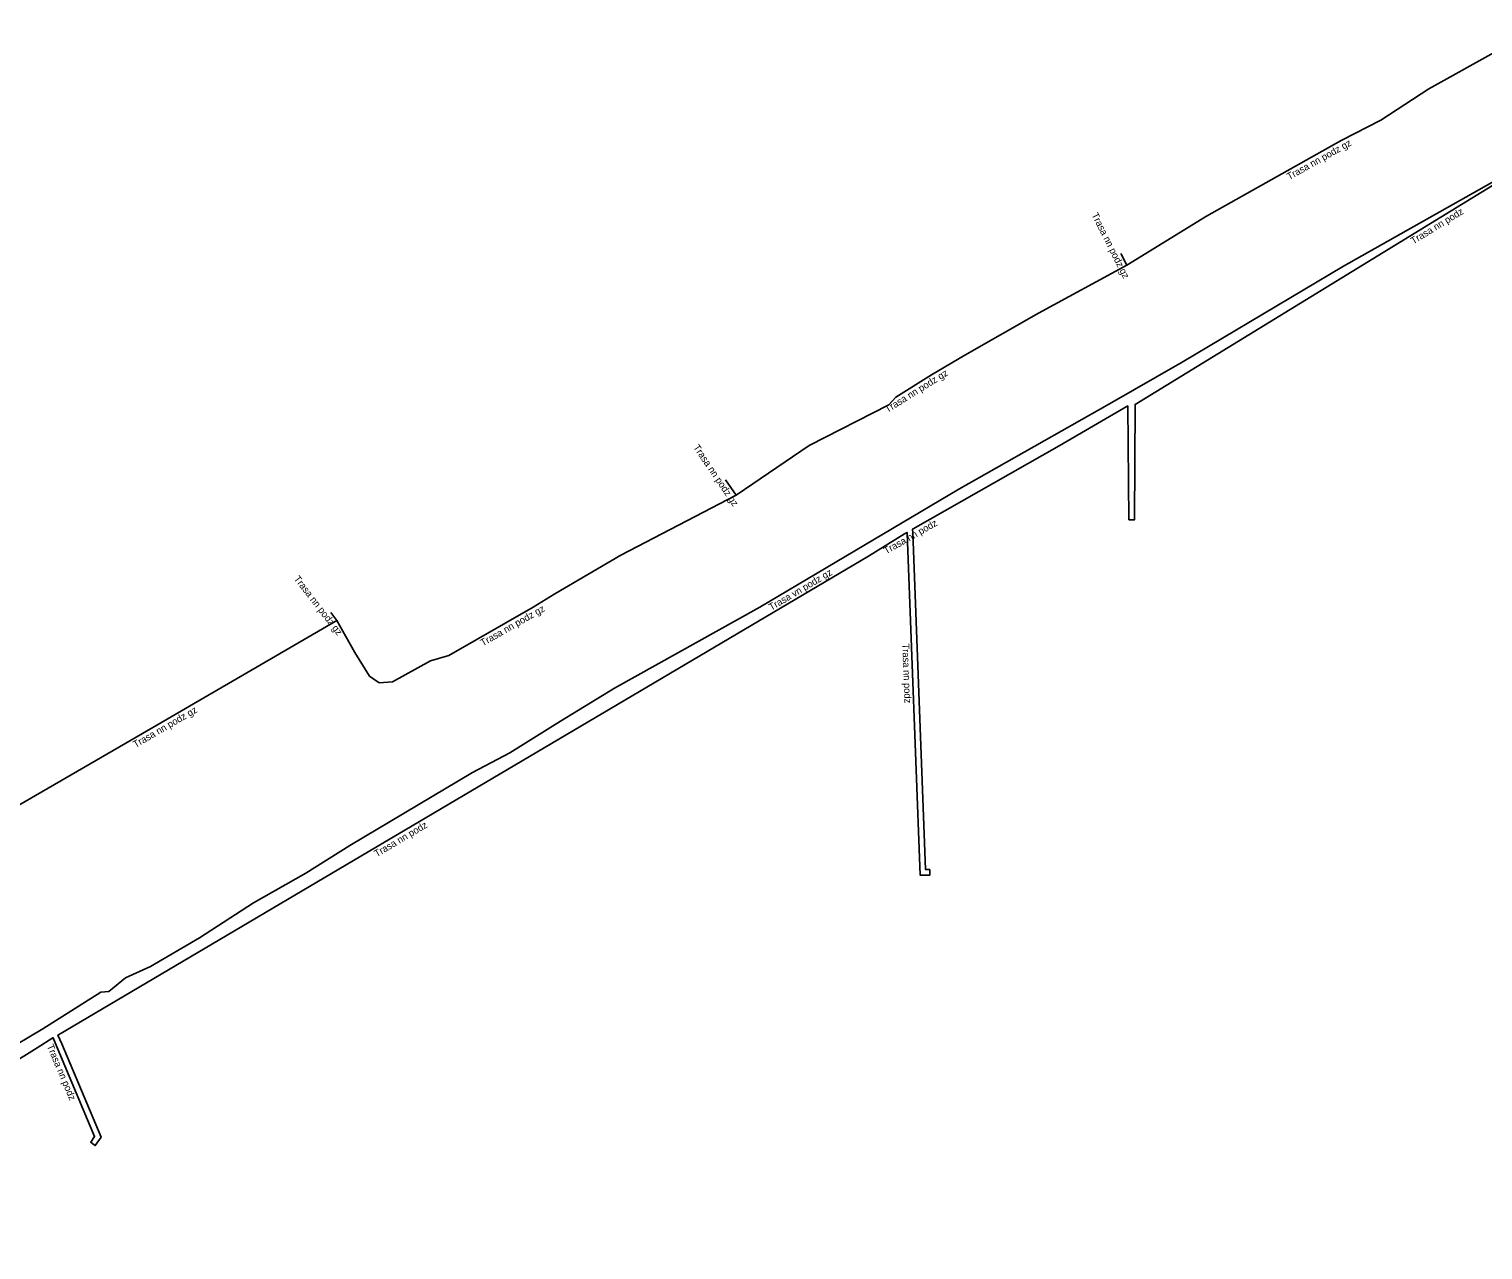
# Model space of a CAD drawing. Extents: x -689216 to -688745, y -973188 to -972893.
# Drawn here: x -688948.2 to -688844.2, y -973043.9 to -972956.5 of the extents above; entities that cross this region are included whole.
import ezdxf

# ---------------------------------------------------------------- set-up
doc = ezdxf.new("R2010")
doc.units = 0
for name, color, linetype in [('Popiskový text - Ostatní atributy Trasy', 7, 'Continuous'), ('Spojnice NN', 7, 'Continuous'), ('Spojnice VN', 7, 'Continuous')]:
    doc.layers.add(name, color=color, linetype=linetype)

msp = doc.modelspace()

# ---------------------------------------------------------------- linework, layer by layer
at = {"layer": 'Spojnice NN'}
for points in [[(-688840.16, -972956.53), (-688842.96, -972957.97), (-688848.07, -972960.8), (-688851.49, -972963.04), (-688854.33, -972964.51), (-688863.98, -972969.92), (-688869.68, -972973.41)], [(-688869.32, -972991.63), (-688869.12, -972991.63), (-688869.08, -972983.38), (-688831.68, -972960.46), (-688826.91, -972957.72), (-688826.8, -972968.65), (-688827.11, -972968.48)], [(-688869.68, -972973.41), (-688870.09, -972972.59)], [(-688869.68, -972973.41), (-688876, -972976.84), (-688881.26, -972979.86), (-688883.65, -972981.26), (-688886.2, -972982.85), (-688886.69, -972983.4), (-688892.41, -972986.32), (-688897.63, -972989.87)], [(-688883.77, -973016.85), (-688883.77, -973016.65), (-688884.07, -973016.65), (-688884.99, -972992.57), (-688885, -972992.29), (-688884.96, -972992.27), (-688874.51, -972986.34), (-688869.61, -972983.48), (-688869.52, -972991.63), (-688869.32, -972991.63)], [(-688897.63, -972989.87), (-688898.38, -972988.76)], [(-688897.63, -972989.87), (-688905.87, -972994.17), (-688910.61, -972996.93), (-688912.14, -972997.88), (-688918.18, -973001.33), (-688919.5, -973001.72), (-688922.22, -973003.22), (-688923.18, -973003.29), (-688923.86, -973002.81), (-688924.92, -973001.12), (-688926.19, -972998.83)], [(-688888.15, -972994.24), (-688885.57, -972992.64), (-688885.39, -972992.53), (-688885.39, -972992.58), (-688884.45, -973017.05), (-688883.77, -973017.05), (-688883.77, -973016.85)], [(-688943.65, -973036.27), (-688943.48, -973036.39), (-688943.07, -973035.8), (-688945.88, -973029.12), (-688946.15, -973028.49), (-688946.12, -973028.47), (-688888.15, -972994.24)], [(-688948.94, -973012.04), (-688940.11, -973006.92), (-688926.19, -972998.83)], [(-688926.19, -972998.83), (-688926.63, -972998.26)], [(-688943.65, -973036.27), (-688943.81, -973036.16), (-688943.53, -973035.75), (-688946.47, -973028.76), (-688946.5, -973028.68), (-688946.51, -973028.69), (-688947.65, -973029.4)], [(-688947.65, -973029.4), (-688969.38, -973042.94), (-688981.43, -973049.44), (-689025, -973075.49), (-689031.28, -973079.02), (-689037.83, -973082.74)]]:
    msp.add_lwpolyline(points, dxfattribs=at)
at = {"layer": 'Spojnice VN'}
msp.add_lwpolyline([(-688842.63, -972966.98), (-688854.17, -972973.49), (-688865.72, -972980.36), (-688870.91, -972983.34), (-688881.69, -972989.45), (-688895.93, -972997.87), (-688906.33, -973003.68), (-688910.19, -973006.04), (-688913.82, -973008.31), (-688916.49, -973009.71), (-688925.26, -973014.93), (-688928.41, -973016.9), (-688932.17, -973019.03), (-688936.02, -973021.53), (-688939.52, -973023.58), (-688941.33, -973024.4), (-688942.51, -973025.36), (-688943.09, -973025.43), (-688947.24, -973028.03), (-688950.11, -973029.76)], dxfattribs=at)

# ---------------------------------------------------------------- texts
at = {"layer": 'Popiskový text - Ostatní atributy Trasy'}
for s, rotation, p in [('Trasa nn podz gz', 29.2759, (-688858.05, -972967.34)), ('Trasa nn podz gz', 296.5651, (-688872.21, -972969.81)), ('Trasa nn podz', 31.4982, (-688849.17, -972971.94)), ('Trasa nn podz gz', 31.9448, (-688886.8, -972983.99)), ('Trasa nn podz gz', 304.0459, (-688900.72, -972986.45)), ('Trasa nn podz', 29.5592, (-688886.89, -972994.11)), ('Trasa nn podz gz', 307.6656, (-688929.3, -972995.86)), ('Trasa vn podz gz', 30.5955, (-688895.11, -972998.14)), ('Trasa nn podz gz', 29.7347, (-688915.75, -973000.69)), ('Trasa nn podz', 272.1982, (-688885.74, -973000.49)), ('Trasa nn podz gz', 30.1642, (-688940.6, -973007.96)), ('Trasa nn podz', 30.567, (-688923.34, -973015.77)), ('Trasa nn podz', 292.8285, (-688946.96, -973029.27))]:
    msp.add_text(s, height=0.5, rotation=rotation, dxfattribs=at).set_placement(p)

doc.saveas('drawing.dxf')
